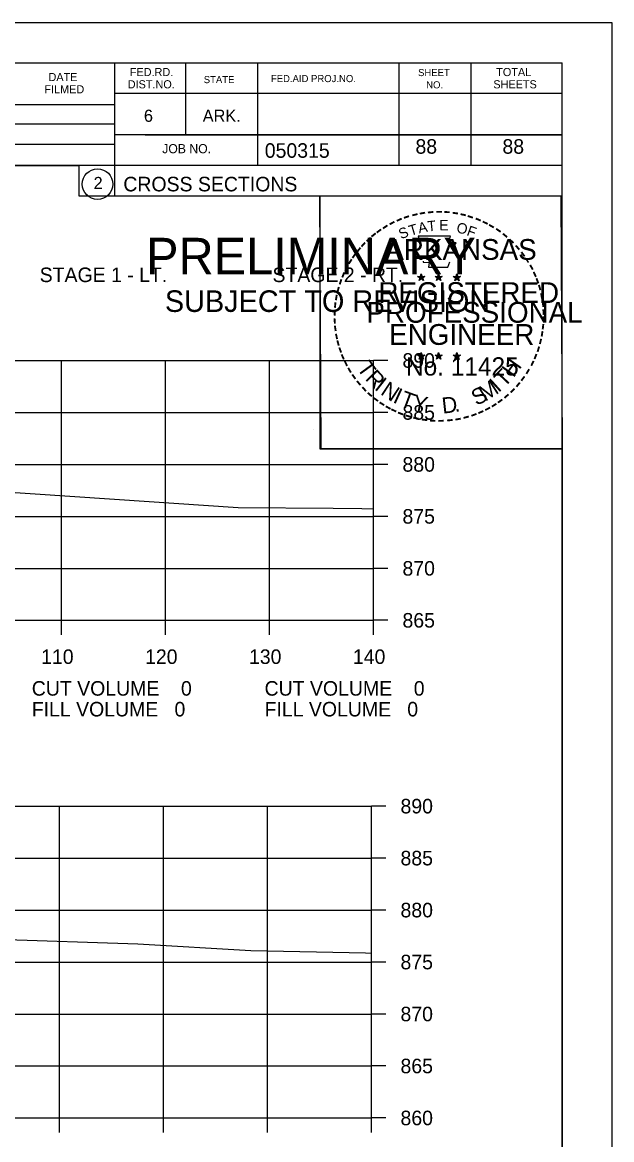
# Model space of a CAD drawing. Extents: x 1486524 to 1499135, y 326561 to 337924.
# Drawn here: x 1489089.1 to 1489145.8, y 336298.6 to 336406.1 of the extents above; entities that cross this region are included whole.
import ezdxf

# ---------------------------------------------------------------- set-up
doc = ezdxf.new("R2010")
doc.units = 0
for name, color, linetype in [('Default', 7, 'Continuous'), ('E_Const Align', 7, 'Continuous'), ('E_Const Align Station', 7, 'Continuous'), ('E_Ownership Information', 7, 'Continuous'), ('E_Property Line', 7, 'Continuous'), ('E_Quarter Calls', 7, 'Continuous'), ('E_Section Line', 7, 'Continuous'), ('E_Station Offset', 7, 'Continuous'), ('E_Tract Number', 7, 'Continuous'), ('S_SIXTEEN_SECTION', 7, 'Continuous')]:
    doc.layers.add(name, color=color, linetype=linetype)

msp = doc.modelspace()

# ---------------------------------------------------------------- linework, layer by layer
at = {"layer": 'E_Const Align'}
for p, q in [((1489122.89, 336348.52), (1489122.89, 336373.52)), ((1489124.29, 336373.52), (1489122.89, 336373.52)), ((1489124.29, 336368.52), (1489122.89, 336368.52)), ((1489124.29, 336363.52), (1489122.89, 336363.52)), ((1489124.29, 336358.52), (1489122.89, 336358.52)), ((1489124.29, 336353.52), (1489122.89, 336353.52)), ((1488842.89, 336348.52), (1489122.89, 336348.52)), ((1489092.89, 336347.12), (1489092.89, 336348.52)), ((1489102.89, 336347.12), (1489102.89, 336348.52)), ((1489112.89, 336347.12), (1489112.89, 336348.52)), ((1489122.89, 336347.12), (1489122.89, 336348.52)), ((1489124.29, 336348.52), (1489122.89, 336348.52)), ((1489122.7, 336300.64), (1489122.7, 336330.64)), ((1489124.1, 336330.64), (1489122.7, 336330.64)), ((1489124.1, 336325.64), (1489122.7, 336325.64)), ((1489124.1, 336320.64), (1489122.7, 336320.64)), ((1489124.1, 336315.64), (1489122.7, 336315.64)), ((1489124.1, 336310.64), (1489122.7, 336310.64)), ((1489124.1, 336305.64), (1489122.7, 336305.64)), ((1488842.7, 336300.64), (1489122.7, 336300.64)), ((1489092.7, 336299.24), (1489092.7, 336300.64)), ((1489102.7, 336299.24), (1489102.7, 336300.64)), ((1489112.7, 336299.24), (1489112.7, 336300.64)), ((1489122.7, 336299.24), (1489122.7, 336300.64)), ((1489124.1, 336300.64), (1489122.7, 336300.64))]:
    msp.add_line(p, q, dxfattribs=at)
at = {"layer": 'E_Ownership Information'}
for p, q in [((1488842.89, 336373.52), (1489122.89, 336373.52)), ((1488842.89, 336373.52), (1489122.89, 336373.52)), ((1489092.89, 336348.52), (1489092.89, 336373.52)), ((1489092.89, 336348.52), (1489092.89, 336373.52)), ((1489102.89, 336348.52), (1489102.89, 336373.52)), ((1489102.89, 336348.52), (1489102.89, 336373.52)), ((1489112.89, 336348.52), (1489112.89, 336373.52)), ((1489112.89, 336348.52), (1489112.89, 336373.52)), ((1489122.89, 336348.52), (1489122.89, 336373.52)), ((1489122.89, 336348.52), (1489122.89, 336373.52)), ((1488842.89, 336368.52), (1489122.89, 336368.52)), ((1488842.89, 336368.52), (1489122.89, 336368.52)), ((1488842.89, 336363.52), (1489122.89, 336363.52)), ((1488842.89, 336363.52), (1489122.89, 336363.52)), ((1488842.89, 336358.52), (1489122.89, 336358.52)), ((1488842.89, 336358.52), (1489122.89, 336358.52)), ((1488842.89, 336353.52), (1489122.89, 336353.52)), ((1488842.89, 336353.52), (1489122.89, 336353.52)), ((1488842.89, 336348.52), (1489122.89, 336348.52)), ((1488842.89, 336348.52), (1489122.89, 336348.52)), ((1488842.7, 336330.64), (1489122.7, 336330.64)), ((1489092.7, 336300.64), (1489092.7, 336330.64)), ((1489102.7, 336300.64), (1489102.7, 336330.64)), ((1489112.7, 336300.64), (1489112.7, 336330.64)), ((1489122.7, 336300.64), (1489122.7, 336330.64)), ((1488842.7, 336325.64), (1489122.7, 336325.64)), ((1488842.7, 336320.64), (1489122.7, 336320.64)), ((1488842.7, 336315.64), (1489122.7, 336315.64)), ((1488842.7, 336310.64), (1489122.7, 336310.64)), ((1488842.7, 336305.64), (1489122.7, 336305.64)), ((1488842.7, 336300.64), (1489122.7, 336300.64))]:
    msp.add_line(p, q, dxfattribs=at)
at = {"layer": 'E_Property Line'}
for p, q in [((1488824.89, 336402.16), (1489141.07, 336402.16)), ((1489097.97, 336402.16), (1489097.97, 336389.36)), ((1489104.81, 336402.16), (1489104.81, 336395.22)), ((1489111.75, 336402.16), (1489111.75, 336392.28)), ((1489125.33, 336402.16), (1489125.33, 336392.28)), ((1489132.27, 336402.16), (1489132.27, 336392.28)), ((1489141.07, 336196.7), (1489141.07, 336402.16)), ((1489141.07, 336399.22), (1489097.97, 336399.22)), ((1489141.07, 336399.24), (1489141.07, 336399.24)), ((1489058.81, 336398.14), (1489097.97, 336398.14)), ((1489058.81, 336396.28), (1489097.97, 336396.28)), ((1489058.81, 336394.34), (1489097.97, 336394.34)), ((1489141.07, 336395.22), (1489097.97, 336395.22)), ((1489100.93, 336395.22), (1489141.07, 336395.22)), ((1489141.07, 336392.28), (1489058.81, 336392.28)), ((1489097.97, 336389.36), (1489141.07, 336389.36))]:
    msp.add_line(p, q, dxfattribs=at)
msp.add_circle((1489096.35, 336390.49), 1.47, dxfattribs=at)
at = {"layer": 'E_Quarter Calls'}
for p, q in [((1488812.48, 336406.05), (1489145.82, 336406.05)), ((1489117.1, 336366.9), (1489117.1, 336366.9))]:
    msp.add_line(p, q, dxfattribs=at)
for points in [[(1488812.48, 336406.05), (1489145.82, 336406.05), (1489145.82, 336192.71), (1488812.48, 336192.71)], [(1489058.81, 336402.16), (1489058.81, 336392.28), (1489094.54, 336392.28), (1489094.54, 336389.36), (1489117.74, 336389.36), (1489117.74, 336365.02), (1489141.07, 336365.02), (1489141.07, 336196.7), (1488824.89, 336196.7), (1488824.89, 336402.16)], [(1489117.74, 336389.36), (1489140.94, 336389.36), (1489141.07, 336365.02), (1489117.86, 336365.02)]]:
    msp.add_lwpolyline(points, close=True, dxfattribs=at)
at = {"layer": 'E_Tract Number'}
for points in [[(1489025.15, 336362.09), (1489043.89, 336360.91), (1489044.97, 336360.84), (1489045.57, 336360.82), (1489056.46, 336360.72), (1489072.18, 336360.54), (1489074.59, 336360.62), (1489086.02, 336360.98), (1489097.97, 336360.18), (1489109.87, 336359.37), (1489119.02, 336359.3), (1489121.78, 336359.28), (1489122.89, 336359.25)], [(1489033.86, 336317.46), (1489038.83, 336317.38), (1489040.39, 336317.41), (1489047.18, 336317.44), (1489055.91, 336317.46), (1489062.17, 336317.48), (1489070.93, 336317.49), (1489080.94, 336317.71), (1489086.64, 336317.85), (1489100.23, 336317.39), (1489111.1, 336316.75), (1489122.14, 336316.52), (1489122.7, 336316.51)]]:
    msp.add_lwpolyline(points, dxfattribs=at)
at = {"layer": 'S_SIXTEEN_SECTION'}
for p, q in [((1489127.15, 336381.61), (1489127.5, 336381.5)), ((1489127.15, 336381.61), (1489127.4, 336381.57)), ((1489127.15, 336381.61), (1489127.39, 336381.49)), ((1489127.28, 336381.2), (1489127.5, 336381.5)), ((1489127.28, 336381.2), (1489127.41, 336381.45)), ((1489127.28, 336381.2), (1489127.5, 336381.42)), ((1489127.5, 336381.87), (1489127.46, 336381.61)), ((1489127.5, 336381.5), (1489127.5, 336381.87)), ((1489127.5, 336381.87), (1489127.55, 336381.62)), ((1489127.85, 336381.61), (1489127.5, 336381.5)), ((1489127.71, 336381.2), (1489127.5, 336381.5)), ((1489127.71, 336381.2), (1489127.5, 336381.42)), ((1489127.85, 336381.61), (1489127.56, 336381.56)), ((1489127.71, 336381.2), (1489127.58, 336381.5)), ((1489127.85, 336381.61), (1489127.64, 336381.51)), ((1489128.82, 336381.61), (1489129.17, 336381.5)), ((1489128.82, 336381.61), (1489129.07, 336381.57)), ((1489128.82, 336381.61), (1489129.06, 336381.49)), ((1489128.95, 336381.2), (1489129.17, 336381.5)), ((1489128.95, 336381.2), (1489129.08, 336381.45)), ((1489128.95, 336381.2), (1489129.17, 336381.42)), ((1489129.17, 336381.87), (1489129.13, 336381.61)), ((1489129.17, 336381.5), (1489129.17, 336381.87)), ((1489129.17, 336381.87), (1489129.22, 336381.62)), ((1489129.52, 336381.61), (1489129.17, 336381.5)), ((1489129.38, 336381.2), (1489129.17, 336381.5)), ((1489129.38, 336381.2), (1489129.17, 336381.42)), ((1489129.52, 336381.61), (1489129.23, 336381.56)), ((1489129.38, 336381.2), (1489129.25, 336381.5)), ((1489129.52, 336381.61), (1489129.31, 336381.51)), ((1489130.58, 336381.6), (1489130.93, 336381.49)), ((1489130.58, 336381.6), (1489130.84, 336381.56)), ((1489130.58, 336381.6), (1489130.82, 336381.48)), ((1489130.72, 336381.19), (1489130.93, 336381.49)), ((1489130.72, 336381.19), (1489130.84, 336381.44)), ((1489130.72, 336381.19), (1489130.93, 336381.41)), ((1489130.93, 336381.85), (1489130.89, 336381.6)), ((1489130.93, 336381.49), (1489130.93, 336381.85)), ((1489130.93, 336381.85), (1489130.98, 336381.6)), ((1489131.28, 336381.6), (1489130.93, 336381.49)), ((1489131.15, 336381.19), (1489130.93, 336381.49)), ((1489131.15, 336381.19), (1489130.93, 336381.41)), ((1489131.28, 336381.6), (1489130.99, 336381.55)), ((1489131.15, 336381.19), (1489131.01, 336381.48)), ((1489131.28, 336381.6), (1489131.08, 336381.5)), ((1489127.15, 336374.04), (1489127.5, 336373.93)), ((1489127.15, 336374.04), (1489127.4, 336373.99)), ((1489127.15, 336374.04), (1489127.38, 336373.92)), ((1489127.28, 336373.63), (1489127.5, 336373.93)), ((1489127.28, 336373.63), (1489127.41, 336373.88)), ((1489127.28, 336373.63), (1489127.49, 336373.85)), ((1489127.5, 336374.29), (1489127.45, 336374.04)), ((1489127.71, 336373.63), (1489127.49, 336373.85)), ((1489127.5, 336373.93), (1489127.5, 336374.29)), ((1489127.5, 336374.29), (1489127.54, 336374.04)), ((1489127.84, 336374.04), (1489127.5, 336373.93)), ((1489127.71, 336373.63), (1489127.5, 336373.93)), ((1489127.84, 336374.04), (1489127.56, 336373.99)), ((1489127.71, 336373.63), (1489127.57, 336373.92)), ((1489127.84, 336374.04), (1489127.64, 336373.94)), ((1489128.82, 336374.04), (1489129.16, 336373.93)), ((1489128.82, 336374.04), (1489129.07, 336373.99)), ((1489128.82, 336374.04), (1489129.05, 336373.92)), ((1489128.95, 336373.63), (1489129.16, 336373.93)), ((1489128.95, 336373.63), (1489129.07, 336373.88)), ((1489128.95, 336373.63), (1489129.16, 336373.85)), ((1489129.16, 336374.29), (1489129.12, 336374.04)), ((1489129.16, 336373.93), (1489129.16, 336374.29)), ((1489129.16, 336374.29), (1489129.21, 336374.04)), ((1489129.51, 336374.04), (1489129.16, 336373.93)), ((1489129.38, 336373.63), (1489129.16, 336373.93)), ((1489129.38, 336373.63), (1489129.16, 336373.85)), ((1489129.51, 336374.04), (1489129.23, 336373.99)), ((1489129.38, 336373.63), (1489129.24, 336373.92)), ((1489129.51, 336374.04), (1489129.31, 336373.94)), ((1489130.58, 336374.03), (1489130.93, 336373.92)), ((1489130.58, 336374.03), (1489130.84, 336373.98)), ((1489130.58, 336374.03), (1489130.82, 336373.91)), ((1489130.72, 336373.62), (1489130.93, 336373.92)), ((1489130.72, 336373.62), (1489130.84, 336373.87)), ((1489130.72, 336373.62), (1489130.93, 336373.84)), ((1489130.93, 336374.28), (1489130.89, 336374.03)), ((1489130.93, 336373.92), (1489130.93, 336374.28)), ((1489130.93, 336374.28), (1489130.98, 336374.03)), ((1489131.28, 336374.03), (1489130.93, 336373.92)), ((1489131.14, 336373.62), (1489130.93, 336373.92)), ((1489131.14, 336373.62), (1489130.93, 336373.84)), ((1489131.28, 336374.03), (1489130.99, 336373.98)), ((1489131.14, 336373.62), (1489131.01, 336373.91)), ((1489131.28, 336374.03), (1489131.07, 336373.93))]:
    msp.add_line(p, q, dxfattribs=at)
for points in [[(1489127.19, 336385.49), (1489127.46, 336384.66)], [(1489130.7, 336384.57), (1489130.84, 336384.85), (1489130.16, 336384.83), (1489130.31, 336385.49), (1489127.19, 336385.49)], [(1489127.68, 336383.07), (1489127.68, 336382.98), (1489128.25, 336382.96), (1489128.19, 336382.49), (1489130.06, 336382.49), (1489130.26, 336383.02)], [(1489127.5, 336381.87), (1489127.71, 336381.2), (1489127.15, 336381.61), (1489127.85, 336381.61), (1489127.28, 336381.2), (1489127.5, 336381.87)], [(1489129.17, 336381.87), (1489129.38, 336381.2), (1489128.82, 336381.61), (1489129.52, 336381.61), (1489128.95, 336381.2), (1489129.17, 336381.87)], [(1489130.93, 336381.85), (1489131.15, 336381.19), (1489130.58, 336381.6), (1489131.28, 336381.6), (1489130.72, 336381.19), (1489130.93, 336381.85)], [(1489127.5, 336374.29), (1489127.71, 336373.63), (1489127.15, 336374.04), (1489127.84, 336374.04), (1489127.28, 336373.63), (1489127.5, 336374.29)], [(1489129.16, 336374.29), (1489129.38, 336373.63), (1489128.82, 336374.04), (1489129.51, 336374.04), (1489128.95, 336373.63), (1489129.16, 336374.29)], [(1489130.93, 336374.28), (1489131.14, 336373.62), (1489130.58, 336374.03), (1489131.28, 336374.03), (1489130.72, 336373.62), (1489130.93, 336374.28)]]:
    msp.add_lwpolyline(points, dxfattribs=at)
for centre, radius in [((1489127.5, 336381.5), 0.172), ((1489127.5, 336381.5), 0.145), ((1489127.5, 336381.5), 0.116), ((1489127.5, 336381.5), 0.0991), ((1489127.5, 336381.5), 0.0747), ((1489127.5, 336381.5), 0.0495), ((1489127.5, 336381.5), 0.0296), ((1489129.17, 336381.5), 0.172), ((1489129.17, 336381.5), 0.145), ((1489129.17, 336381.5), 0.116), ((1489129.17, 336381.5), 0.0991), ((1489129.17, 336381.5), 0.0747), ((1489129.17, 336381.5), 0.0495), ((1489129.17, 336381.5), 0.0296), ((1489130.93, 336381.49), 0.172), ((1489130.93, 336381.49), 0.145), ((1489130.93, 336381.49), 0.116), ((1489130.93, 336381.49), 0.0991), ((1489130.93, 336381.49), 0.0747), ((1489130.93, 336381.49), 0.0495), ((1489130.93, 336381.49), 0.0296), ((1489127.49, 336373.93), 0.172), ((1489127.49, 336373.93), 0.145), ((1489127.49, 336373.93), 0.116), ((1489127.49, 336373.93), 0.0991), ((1489127.49, 336373.93), 0.0747), ((1489127.49, 336373.93), 0.0495), ((1489127.49, 336373.93), 0.0296), ((1489129.16, 336373.93), 0.172), ((1489129.16, 336373.93), 0.145), ((1489129.16, 336373.93), 0.116), ((1489129.16, 336373.93), 0.0991), ((1489129.16, 336373.93), 0.0747), ((1489129.16, 336373.93), 0.0495), ((1489129.16, 336373.93), 0.0296), ((1489130.93, 336373.92), 0.172), ((1489130.93, 336373.92), 0.145), ((1489130.93, 336373.92), 0.116), ((1489130.93, 336373.92), 0.0991), ((1489130.93, 336373.92), 0.0747), ((1489130.93, 336373.92), 0.0495), ((1489130.93, 336373.92), 0.0296)]:
    msp.add_circle(centre, radius, dxfattribs=at)

# ---------------------------------------------------------------- texts
at = {"layer": 'Default'}
for s, p in [('STAGE 1 - LT.', (1489090.78, 336381.06)), ('STAGE 2 - RT.', (1489113.18, 336381.06))]:
    msp.add_text(s, height=1.4, dxfattribs=at).set_placement(p)
at = {"layer": 'E_Const Align Station'}
for s, p in [('890', (1489125.69, 336372.82)), ('885', (1489125.69, 336367.82)), ('880', (1489125.69, 336362.82)), ('875', (1489125.69, 336357.82)), ('870', (1489125.69, 336352.82)), ('865', (1489125.69, 336347.82)), ('110', (1489090.92, 336344.32)), ('120', (1489100.92, 336344.32)), ('130', (1489110.92, 336344.32)), ('140', (1489120.92, 336344.32)), ('CUT VOLUME    0', (1489090.02, 336341.27)), ('CUT VOLUME    0', (1489112.42, 336341.27)), ('FILL VOLUME   0', (1489090.02, 336339.27)), ('FILL VOLUME   0', (1489112.42, 336339.27)), ('890', (1489125.5, 336329.94)), ('885', (1489125.5, 336324.94)), ('880', (1489125.5, 336319.94)), ('875', (1489125.5, 336314.94)), ('870', (1489125.5, 336309.94)), ('865', (1489125.5, 336304.94)), ('860', (1489125.5, 336299.94))]:
    msp.add_text(s, height=1.4, dxfattribs=at).set_placement(p)
at = {"layer": 'E_Property Line'}
for s, height, p in [('DATE', 0.782, (1489091.63, 336400.4)), ('FED.RD.', 0.782, (1489099.45, 336400.88)), ('STATE', 0.684, (1489106.57, 336400.2)), ('FED.AID PROJ.NO.', 0.684, (1489113.03, 336400.3)), ('SHEET', 0.684, (1489127.19, 336400.88)), ('TOTAL', 0.782, (1489134.71, 336400.88)), ('FILMED', 0.782, (1489091.23, 336399.22)), ('DIST.NO.', 0.782, (1489099.25, 336399.7)), ('NO.', 0.684, (1489127.97, 336399.7)), ('SHEETS', 0.782, (1489134.43, 336399.7)), ('6', 1.17, (1489100.81, 336396.48)), ('ARK.', 1.172, (1489106.47, 336396.48)), ('JOB NO.', 0.879, (1489102.57, 336393.46)), ('050315', 1.4, (1489112.44, 336393.02)), ('2', 1.17, (1489095.97, 336390.01)), ('CROSS SECTIONS', 1.4, (1489098.83, 336389.79))]:
    msp.add_text(s, height=height, rotation=360, dxfattribs=at).set_placement(p)
at = {"layer": 'E_Section Line'}
for s, height, p in [('PRELIMINARY', 3.5, (1489101.02, 336381.82)), ('DWB', 0.01, (1489101.76, 336383.67)), ('SUBJECT TO REVISION', 2.0751, (1489102.83, 336378.19))]:
    msp.add_text(s, height=height, rotation=360, dxfattribs=at).set_placement(p)
at = {"layer": 'E_Station Offset'}
for p in [(1489126.94, 336393.41), (1489135.31, 336393.41)]:
    msp.add_text('88', height=1.4, dxfattribs=at).set_placement(p)
at = {"layer": 'S_SIXTEEN_SECTION'}
for s, height, rotation, p in [('-', 1.6, 10.2193, (1489127.37, 336387.02)), ('-', 1.6, 5.8968, (1489128.1, 336387.13)), ('-', 1.6, 0.1862, (1489128.87, 336387.2)), ('-', 1.6, 357.743, (1489129.59, 336387.19)), ('-', 1.6, 352.1617, (1489130.34, 336387.13)), ('-', 1.6, 28.7918, (1489124.67, 336386.03)), ('-', 1.6, 24.3072, (1489125.31, 336386.35)), ('-', 1.6, 19.1761, (1489125.94, 336386.62)), ('-', 1.6, 13.6301, (1489126.69, 336386.86)), ('A', 1, 11.2132, (1489127.29, 336385.75)), ('T', 1, 6.0228, (1489128.14, 336385.92)), ('E', 1, 0.8323, (1489129.24, 336386.03)), ('O', 1, 350.4515, (1489130.84, 336385.82)), ('-', 1.6, 347.2049, (1489131.05, 336387.02)), ('-', 1.6, 342.3362, (1489131.69, 336386.86)), ('-', 1.6, 337.8551, (1489132.42, 336386.64)), ('-', 1.6, 334.1211, (1489133.06, 336386.37)), ('-', 1.6, 38.9507, (1489123.02, 336384.89)), ('-', 1.6, 36.2317, (1489123.5, 336385.27)), ('-', 1.6, 34.0636, (1489124.08, 336385.66)), ('S', 1, 21.594, (1489125.55, 336385.17)), ('T', 1, 16.4036, (1489126.46, 336385.5)), ('F', 1, 340.0707, (1489131.8, 336385.59)), ('-', 1.6, 329.6409, (1489133.63, 336386.09)), ('-', 1.6, 325.8627, (1489134.28, 336385.73)), ('-', 1.6, 320.5297, (1489134.89, 336385.3)), ('-', 1.6, 48.423, (1489122.14, 336383.99)), ('-', 1.6, 42.9622, (1489122.59, 336384.47)), ('ARKANSAS', 2, 360, (1489124.04, 336383.2)), ('-', 1.6, 315.5786, (1489135.49, 336384.81)), ('-', 1.6, 309.8797, (1489136.06, 336384.26)), ('-', 1.6, 54.2325, (1489121.32, 336382.94)), ('-', 1.6, 50.6142, (1489121.74, 336383.51)), ('-', 1.6, 306.6522, (1489136.58, 336383.66)), ('-', 1.6, 62.8713, (1489120.69, 336381.8)), ('-', 1.6, 58.0706, (1489121, 336382.41)), ('-', 1.4, 303.6753, (1489137.07, 336383.09)), ('-', 1.6, 299.6684, (1489137.39, 336382.49)), ('-', 1.6, 72.3945, (1489120.21, 336380.56)), ('-', 1.6, 67.7743, (1489120.43, 336381.19)), ('DWB', 0.01, 360, (1489127.49, 336381.5)), ('DWB', 0.01, 360, (1489129.16, 336381.5)), ('DWB', 0.01, 360, (1489130.92, 336381.49)), ('-', 1.6, 294.6628, (1489137.71, 336381.87)), ('-', 1.6, 290.5728, (1489137.97, 336381.3)), ('-', 1.6, 75.461, (1489120.01, 336379.84)), ('REGISTERED', 2, 360, (1489123.37, 336379.05)), ('-', 1.6, 285.1233, (1489138.2, 336380.72)), ('-', 1.6, 81.2013, (1489119.88, 336379.13)), ('-', 1.6, 280.5493, (1489138.4, 336379.97)), ('-', 1.6, 89.0622, (1489119.78, 336377.74)), ('-', 1.6, 85.1863, (1489119.8, 336378.44)), ('PROFESSIONAL', 2, 360, (1489122.22, 336377.15)), ('-', 1.6, 276.5962, (1489138.56, 336379.21)), ('-', 1.6, 274.3301, (1489138.62, 336378.48)), ('-', 1.6, 94.1959, (1489119.81, 336377.01)), ('-', 1.6, 269.9407, (1489138.66, 336377.85)), ('-', 1.6, 98.9479, (1489119.89, 336376.35)), ('-', 1.6, 101.7149, (1489120.02, 336375.61)), ('ENGINEER', 2, 360, (1489124.41, 336375.02)), ('-', 1.6, 260.9953, (1489138.57, 336376.53)), ('-', 1.6, 263.5172, (1489138.64, 336377.19)), ('-', 1.6, 105.4578, (1489120.18, 336375.02)), ('-', 1.6, 255.7626, (1489138.46, 336375.85)), ('-', 1.6, 109.0874, (1489120.4, 336374.39)), ('-', 1.6, 114.0643, (1489120.65, 336373.79)), ('No. 11425', 1.757, 360, (1489126.03, 336372.07)), ('DWB', 0.01, 360, (1489127.48, 336373.92)), ('DWB', 0.01, 360, (1489129.15, 336373.92)), ('DWB', 0.01, 360, (1489130.92, 336373.91)), ('-', 1.6, 247.8887, (1489138.05, 336374.46)), ('-', 1.6, 252.8681, (1489138.28, 336375.13)), ('-', 1.6, 115.7289, (1489120.96, 336373.17)), ('-', 1.6, 120.4471, (1489121.31, 336372.59)), ('T', 1.54, 306.0406, (1489121.25, 336372.77)), ('T', 1.54, 46.6444, (1489135.49, 336370.86)), ('H', 1.54, 54.6088, (1489136.38, 336371.8)), ('-', 1.6, 244.6197, (1489137.79, 336373.83)), ('-', 1.6, 125.8934, (1489121.72, 336372.03)), ('R', 1.54, 314.005, (1489122.02, 336371.72)), ('I', 1.54, 321.9694, (1489122.92, 336370.79)), ('I', 1.54, 42.1136, (1489134.92, 336370.38)), ('-', 1.6, 233.8452, (1489136.99, 336372.43)), ('-', 1.6, 239.0712, (1489137.4, 336373.08)), ('-', 1.6, 130.7181, (1489122.18, 336371.48)), ('-', 1.6, 134.2238, (1489122.7, 336370.93)), ('N', 1.54, 326.5002, (1489123.49, 336370.31)), ('I', 1.54, 335.3603, (1489124.69, 336369.53)), ('T', 1.54, 339.8912, (1489125.35, 336369.2)), ('S', 1.54, 26.9312, (1489132.8, 336369.13)), ('M', 1.54, 32.6563, (1489133.64, 336369.53)), ('-', 1.6, 225.7653, (1489136.09, 336371.3)), ('-', 1.6, 231.2538, (1489136.56, 336371.86)), ('-', 1.6, 138.9338, (1489123.22, 336370.47)), ('-', 1.6, 144.6463, (1489123.78, 336370.06)), ('-', 1.6, 148.0898, (1489124.34, 336369.69)), ('Y', 1.54, 347.8556, (1489126.57, 336368.76)), ('D', 1.54, 6.3969, (1489129.56, 336368.4)), ('-', 1.6, 215.7363, (1489135.01, 336370.32)), ('-', 1.6, 221.0851, (1489135.56, 336370.79)), ('-', 1.6, 151.5704, (1489124.92, 336369.36)), ('-', 1.6, 154.6002, (1489125.44, 336369.12)), ('-', 1.6, 158.5612, (1489126.06, 336368.86)), ('.', 1.54, 13.7642, (1489130.75, 336368.53)), ('-', 1.6, 200.7184, (1489132.68, 336368.99)), ('-', 1.6, 204.2516, (1489133.3, 336369.26)), ('-', 1.6, 207.3568, (1489133.92, 336369.58)), ('-', 1.6, 212.2491, (1489134.48, 336369.93)), ('-', 1.6, 162.7983, (1489126.75, 336368.65)), ('-', 1.6, 167.5555, (1489127.46, 336368.49)), ('-', 1.6, 173.1155, (1489128.24, 336368.38)), ('-', 1.6, 176.5183, (1489128.98, 336368.32)), ('-', 1.6, 181.5918, (1489129.73, 336368.34)), ('-', 1.6, 185.8167, (1489130.54, 336368.42)), ('-', 1.6, 191.2858, (1489131.27, 336368.55)), ('-', 1.6, 195.4743, (1489132, 336368.75))]:
    msp.add_text(s, height=height, rotation=rotation, dxfattribs=at).set_placement(p)

doc.saveas('drawing.dxf')
